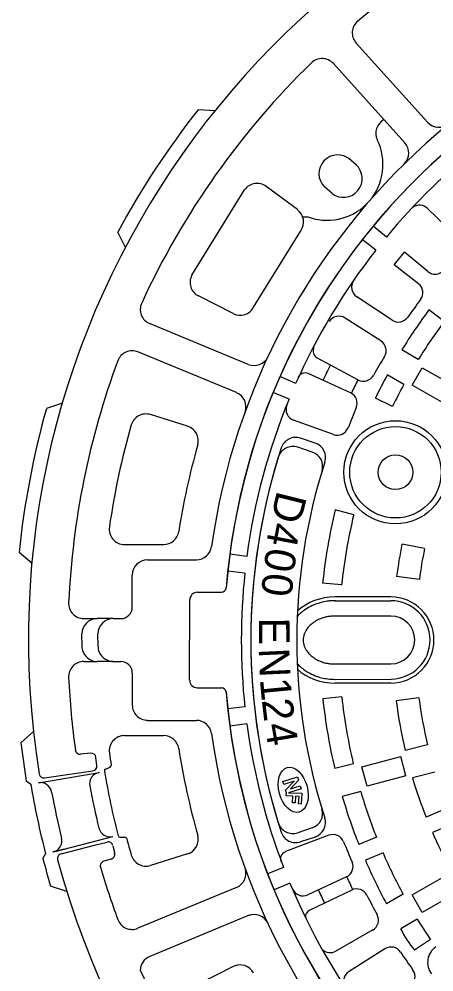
# Model space of a CAD drawing. Extents: x -7.1 to 10, y -5 to 6.
# Drawn here: x -2.462 to -1.897, y 0.265 to 1.564 of the extents above; entities that cross this region are included whole.
import ezdxf

# ---------------------------------------------------------------- set-up
doc = ezdxf.new("R2010")
doc.units = 0
doc.layers.add('Level 1', color=7, linetype='Continuous')

# ---------------------------------------------------------------- blocks, each defined once
blk = doc.blocks.new('CRAN')
at = {"layer": 'Level 1'}
for p, q in [((-3.652, 6.599), (-1.391, 7.083)), ((-3.232, 4.178), (-1.568, 4.4)), ((-1.568, 4.4), (-1.47, 3.52)), ((-3.114, 3.352), (-1.47, 3.52)), ((-2.949, 0.9), (-0.638, 0.965)), ((-2.949, -0.892), (-0.638, -0.957)), ((-3.114, -3.345), (-1.471, -3.52)), ((-1.568, -4.392), (-1.47, -3.512)), ((-3.232, -4.17), (-1.568, -4.392)), ((-3.652, -6.592), (-1.391, -7.076))]:
    blk.add_line(p, q, dxfattribs=at)
for centre, radius, start, end in [((-1.26, 6.472), 0.625, 11.0144, 102.0722), ((-3.521, 5.988), 0.625, 102.0722, 190.9368), ((-34.491, 0.004), 30.918, 8.7409, 10.9368), ((-3.315, 4.797), 0.625, 188.7409, 277.6056), ((-3.048, 2.731), 0.625, 96.0776, 184.9422), ((-34.473, 0.013), 30.918, 2.7463, 4.9422), ((-2.967, 1.524), 0.625, 182.7463, 271.611), ((-0.656, 1.589), 0.625, 271.611, 348.8242), ((-2.967, -1.517), 0.625, 88.389, 177.2537), ((-0.656, -1.582), 0.625, 11.1758, 88.389), ((-34.473, -0.006), 30.918, 355.0578, 357.2537), ((-3.048, -2.723), 0.625, 175.0578, 263.9224), ((-3.315, -4.79), 0.625, 82.3944, 171.2591), ((-34.491, 0.004), 30.918, 349.0632, 351.2591), ((-3.521, -5.981), 0.625, 169.0632, 257.9278), ((-1.26, -6.464), 0.625, 257.9278, 348.9856)]:
    blk.add_arc(centre, radius, start, end, dxfattribs=at)

msp = doc.modelspace()

# ---------------------------------------------------------------- linework, layer by layer
at = {"layer": 'Level 1'}
for p, q in [((-1.9053, 1.4229), (-2.0026, 1.5308)), ((-1.9363, 1.395), (-2.0336, 1.5029)), ((-2.1948, 1.4386), (-2.218, 1.44)), ((-2.002, 1.3642), (-2.0125, 1.3733)), ((-2.2265, 1.2145), (-2.1548, 1.3308)), ((-2.0826, 1.3038), (-2.1254, 1.3354)), ((-2.0353, 1.3257), (-2.0458, 1.3347)), ((-2.3169, 1.2524), (-2.3274, 1.2732)), ((-2.1423, 1.1709), (-2.0781, 1.275)), ((-1.9614, 1.2665), (-1.9795, 1.2814)), ((-1.9759, 1.2486), (-1.9943, 1.263)), ((-2.1701, 1.1622), (-2.2175, 1.1862)), ((-1.9689, 1.1248), (-2.0175, 1.1561)), ((-1.8829, 1.1515), (-1.9035, 1.1674)), ((-2.1496, 1.0929), (-2.2839, 1.1485)), ((-2.1656, 1.0544), (-2.2998, 1.11)), ((-1.918, 1.0996), (-1.9404, 1.1128)), ((-2.0002, 1.0719), (-2.056, 1.1019)), ((-2.0104, 1.0542), (-2.0681, 1.0804)), ((-1.9376, 1.0657), (-1.9602, 1.0788)), ((-1.9263, 1.0647), (-1.9126, 1.0884)), ((-1.9126, 1.0884), (-1.8652, 1.061)), ((-2.085, 1.0668), (-2.1065, 1.0763)), ((-2.0941, 1.0456), (-2.1158, 1.0546)), ((-1.8789, 1.0374), (-1.9263, 1.0647)), ((-2.4025, 1.0401), (-2.4245, 1.0326)), ((-1.953, 1.0357), (-1.9765, 1.0471)), ((-2.2322, 1.0087), (-2.2828, 1.0245)), ((-2.0336, 0.9973), (-2.0879, 1.017)), ((-2.0585, 0.9857), (-2.0783, 0.9923)), ((-2.0624, 0.9733), (-2.0822, 0.9799)), ((-2.006, 0.888), (-2.0311, 0.8948)), ((-2.3182, 0.8475), (-2.2649, 0.8475)), ((-1.9096, 0.8418), (-1.9402, 0.848)), ((-2.444, 0.8214), (-2.4617, 0.8366)), ((-2.1515, 0.8313), (-2.1747, 0.8344)), ((-2.2867, 0.8266), (-2.2203, 0.8266)), ((-2.3075, 0.7621), (-2.3075, 0.8058)), ((-2.1542, 0.8085), (-2.1775, 0.811)), ((-2.0224, 0.7923), (-2.0483, 0.7949)), ((-1.9166, 0.7999), (-1.9476, 0.804)), ((-2.2189, 0.7823), (-2.1862, 0.7823)), ((-2.2295, 0.6626), (-2.2294, 0.7719)), ((-2.0318, 0.7708), (-1.9554, 0.7708)), ((-1.9554, 0.776), (-2.0314, 0.776)), ((-2.3735, 0.7464), (-2.3554, 0.7464)), ((-2.3335, 0.7464), (-2.3554, 0.7464)), ((-2.3335, 0.7464), (-2.3231, 0.7464)), ((-1.9554, 0.7499), (-2.0314, 0.7499)), ((-2.3762, 0.7173), (-2.3762, 0.7256)), ((-2.3762, 0.7172), (-2.3762, 0.7089)), ((-2.3544, 0.7173), (-2.3544, 0.7256)), ((-2.3544, 0.7172), (-2.3544, 0.7089)), ((-2.3735, 0.688), (-2.3554, 0.688)), ((-2.3335, 0.688), (-2.3554, 0.688)), ((-2.3335, 0.688), (-2.3231, 0.688)), ((-2.033, 0.6846), (-1.9553, 0.6848)), ((-2.3075, 0.6724), (-2.3075, 0.6287)), ((-2.0318, 0.6637), (-1.9552, 0.664)), ((-2.2191, 0.6522), (-2.1862, 0.6521)), ((-1.9554, 0.6585), (-2.0314, 0.6585)), ((-2.0222, 0.6398), (-2.0481, 0.6371)), ((-1.9171, 0.6385), (-1.9481, 0.6346)), ((-2.1542, 0.626), (-2.1775, 0.6235)), ((-2.2867, 0.6078), (-2.2203, 0.6078)), ((-2.1515, 0.6032), (-2.1747, 0.6)), ((-2.4419, 0.5925), (-2.4593, 0.5771)), ((-2.3182, 0.587), (-2.2649, 0.587)), ((-1.9056, 0.5746), (-1.9359, 0.5668)), ((-2.3641, 0.563), (-2.378, 0.5616)), ((-1.9948, 0.5445), (-1.9419, 0.5586)), ((-1.9349, 0.5322), (-1.9419, 0.5586)), ((-2.3557, 0.5462), (-2.357, 0.5573)), ((-2.0065, 0.5486), (-2.0317, 0.5421)), ((-2.4353, 0.5227), (-2.3527, 0.5368)), ((-2.4269, 0.5293), (-2.3612, 0.539)), ((-2.344, 0.5415), (-2.3379, 0.5441)), ((-1.9877, 0.518), (-1.9948, 0.5445)), ((-1.8957, 0.5374), (-1.9259, 0.5294)), ((-2.4519, 0.5252), (-2.4459, 0.5209)), ((-2.1024, 0.5243), (-2.0824, 0.5306)), ((-2.1012, 0.5203), (-2.1024, 0.5243)), ((-2.0873, 0.5248), (-2.1012, 0.5203)), ((-2.0988, 0.5126), (-2.0873, 0.5248)), ((-2.081, 0.5262), (-2.0922, 0.5144)), ((-2.0824, 0.5306), (-2.081, 0.5262)), ((-1.9349, 0.5322), (-1.9877, 0.518)), ((-2.0976, 0.5088), (-2.0988, 0.5126)), ((-2.0978, 0.505), (-2.0976, 0.5088)), ((-2.0774, 0.5146), (-2.0947, 0.5092)), ((-2.0947, 0.5092), (-2.0767, 0.5084)), ((-2.0922, 0.5144), (-2.0787, 0.5187)), ((-2.0787, 0.5187), (-2.0774, 0.5146)), ((-2.0767, 0.5084), (-2.0774, 0.4937)), ((-1.9964, 0.5107), (-2.0216, 0.504)), ((-2.0889, 0.5046), (-2.0978, 0.505)), ((-2.0893, 0.4955), (-2.0889, 0.5046)), ((-2.0856, 0.4954), (-2.0893, 0.4955)), ((-2.0852, 0.5045), (-2.0856, 0.4954)), ((-2.0805, 0.5042), (-2.0852, 0.5045)), ((-2.081, 0.4939), (-2.0805, 0.5042)), ((-2.0774, 0.4937), (-2.081, 0.4939)), ((-1.8785, 0.4879), (-1.9074, 0.476)), ((-2.0625, 0.4612), (-2.0822, 0.4546)), ((-1.8698, 0.467), (-1.8987, 0.455)), ((-2.4128, 0.4291), (-2.3339, 0.4495)), ((-2.3592, 0.4375), (-2.3419, 0.4419)), ((-2.3244, 0.4487), (-2.3177, 0.4488)), ((-2.0397, 0.4511), (-2.0991, 0.4289)), ((-2.0585, 0.4488), (-2.0783, 0.4422)), ((-1.9749, 0.4484), (-1.999, 0.4385)), ((-2.4001, 0.4324), (-2.4151, 0.4285)), ((-2.4046, 0.4258), (-2.3592, 0.4375)), ((-2.334, 0.437), (-2.3315, 0.4265)), ((-2.4293, 0.4194), (-2.4256, 0.4258)), ((-2.4151, 0.4285), (-2.416, 0.4282)), ((-2.3361, 0.4187), (-2.3464, 0.4157)), ((-2.2322, 0.4258), (-2.2828, 0.41)), ((-1.9661, 0.4271), (-1.9901, 0.4171)), ((-2.1014, 0.4072), (-2.1233, 0.3988)), ((-2.0159, 0.3945), (-2.0683, 0.37)), ((-1.9263, 0.3698), (-1.8789, 0.3971)), ((-2.3966, 0.3745), (-2.4188, 0.3818)), ((-2.1655, 0.3801), (-2.2998, 0.3245)), ((-2.0929, 0.3859), (-2.1145, 0.3769)), ((-2.0086, 0.3765), (-2.0658, 0.3492)), ((-1.9387, 0.3707), (-1.9613, 0.3579)), ((-1.9126, 0.3461), (-1.9263, 0.3698)), ((-1.8652, 0.3734), (-1.9126, 0.3461)), ((-2.1484, 0.3421), (-2.2838, 0.286)), ((-1.9194, 0.3367), (-1.942, 0.3238)), ((-1.9801, 0.3221), (-2.0302, 0.2932)), ((-1.9016, 0.309), (-1.9233, 0.2946)), ((-2.1701, 0.2723), (-2.2175, 0.2483))]:
    msp.add_line(p, q, dxfattribs=at)
for radius in [0.0703, 0.0623, 0.0237]:
    msp.add_circle((-1.9491, 0.9459), radius, dxfattribs=at)
for centre, radius, start, end in [((-1.2973, 0.7173), 1.1516, 195.0717, 189.1227), ((-1.2971, 0.7172), 1.0983, 112.8646, 129.8224), ((-1.2971, 0.7172), 0.9115, 12.3185, 171.9696), ((-1.2971, 0.7172), 0.8854, 5.6674, 175.3947), ((-1.9872, 1.5447), 0.0208, 129.8224, 222.04), ((-1.2971, 0.7172), 0.8854, 114.6615, 175.3947), ((-2.0491, 1.4889), 0.0208, 42.04, 134.2547), ((-1.2971, 0.7172), 1.0983, 134.2189, 155.2815), ((-1.2977, 0.717), 1.1703, 141.8462, 151.6251), ((-1.9551, 1.408), 0.0208, 117.4512, 206.0842), ((-1.8899, 1.4368), 0.0208, 222.04, 309.4803), ((-2.0422, 1.3654), 0.0761, 252.3344, 26.0842), ((-1.2971, 0.7172), 0.862, 128.262, 140.418), ((-1.9518, 1.381), 0.0208, 314.6034, 42.04), ((-2.0279, 1.3529), 0.0255, 48.4395, 225.3147), ((-2.02, 1.3461), 0.0255, 233.0279, 48.4318), ((-2.1378, 1.3187), 0.0208, 53.4552, 144.6097), ((-2.0951, 1.287), 0.0208, 324.6638, 53.4552), ((-2.0716, 1.273), 0.0208, 72.3344, 100.1249), ((-1.2971, 0.7172), 0.862, 141.9456, 156.078), ((-2.2081, 1.2047), 0.0208, 152.0353, 243.1452), ((-2.2759, 1.1677), 0.0208, 155.2815, 247.5), ((-2.1607, 1.1807), 0.0208, 243.1452, 331.9406), ((-2.026, 1.143), 0.0156, 57.2121, 148.2699), ((-1.2971, 0.7172), 0.7552, 143.415, 148.4128), ((-1.2971, 0.7172), 0.7292, 143.4475, 148.3753), ((-1.9774, 1.1117), 0.0156, 328.3474, 57.2121), ((-2.3078, 1.0907), 0.0208, 67.5, 159.7138), ((-2.051, 1.1111), 0.0104, 150.9692, 241.6787), ((-1.2971, 0.7172), 1.0983, 159.7138, 177.3343), ((-2.1416, 1.1121), 0.0208, 247.5, 334.9404), ((-1.2971, 0.7172), 0.8301, 153.1524, 154.7577), ((-1.3061, 0.6979), 0.7729, 148.3474, 150.5433), ((-2.0724, 1.0709), 0.0104, 65.5686, 156.2781), ((-1.9928, 1.0856), 0.0156, 241.6787, 330.5433), ((-1.2971, 0.7172), 0.7552, 151.3995, 154.1013), ((-1.2971, 0.7172), 0.7875, 153.2323, 154.7184), ((-1.2971, 0.7172), 0.7292, 151.4545, 154.1013), ((-2.1735, 1.0351), 0.0208, 340.0635, 67.5), ((-2.0169, 1.0399), 0.0156, 336.704, 65.5686), ((-1.2971, 0.7172), 0.862, 157.6056, 172.3944), ((-1.2976, 0.7168), 1.1703, 164.3462, 174.1251), ((-2.0826, 1.0317), 0.0156, 158.9774, 250.0352), ((-1.2926, 0.7281), 0.7729, 156.704, 158.8998), ((-2.289, 1.0046), 0.0208, 72.6555, 164.0223), ((-1.2949, 0.72), 1.0548, 164.0223, 171.7512), ((-2.2384, 0.9888), 0.0208, 344.0255, 72.6555), ((-2.0283, 1.012), 0.0156, 250.0352, 338.8998), ((-2.0849, 0.9726), 0.0208, 71.5, 162.0405), ((-1.2921, 0.7179), 0.9635, 164.0255, 171.2099), ((-1.2971, 0.7172), 0.849, 162.0405, 197.9595), ((-2.0888, 0.9602), 0.0208, 71.5, 162.9416), ((-2.0651, 0.966), 0.0208, 342.0545, 71.5), ((-1.2971, 0.7172), 0.849, 162.9416, 197.0584), ((-2.069, 0.9536), 0.0208, 342.9788, 71.5), ((-1.2971, 0.7172), 0.7865, 162.0545, 197.9455), ((-1.2971, 0.7172), 0.7552, 166.3995, 174.0937), ((-1.2971, 0.7172), 0.7292, 166.4545, 174.0937), ((-2.3182, 0.8683), 0.0208, 171.7512, 270), ((-2.2649, 0.8683), 0.0208, 270, 351.2099), ((-2.2203, 0.8475), 0.0208, 270, 351.9696), ((-1.2971, 0.7172), 0.6563, 168.5057, 172.4024), ((-1.2971, 0.7172), 0.625, 168.5057, 172.4024), ((-2.2867, 0.8058), 0.0208, 90, 180), ((-1.2971, 0.7172), 0.862, 173.922, 186.078), ((-2.2189, 0.7719), 0.0104, 90, 179.9516), ((-2.1862, 0.7889), 0.00651, 270, 355.3947), ((-1.2975, 0.7168), 0.885, 175.3618, 175.3623), ((-2.3735, 0.7673), 0.0208, 177.3343, 270), ((-1.9554, 0.7174), 0.0586, 359.8576, 90), ((-1.9554, 0.7174), 0.0534, 270.2162, 90.0016), ((-2.3231, 0.7621), 0.0156, 270, 0), ((-2.3554, 0.7256), 0.0208, 90, 180), ((-2.3335, 0.7256), 0.0208, 90, 180), ((-1.9554, 0.7174), 0.0326, 270.1964, 90.0023), ((-1.9554, 0.7173), 0.0586, 270.1038, 0.2462), ((-2.3554, 0.7089), 0.0208, 180.0017, 270.0017), ((-2.3335, 0.7089), 0.0208, 180.0017, 270.0017), ((-2.3735, 0.6672), 0.0208, 90.0017, 182.6674), ((-2.3231, 0.6724), 0.0156, 0.0017, 90.0017), ((-1.2971, 0.7173), 1.0983, 182.6674, 187.8577), ((-2.219, 0.6626), 0.0104, 179.9516, 269.9287), ((-2.1862, 0.6456), 0.00651, 4.6051, 89.9287), ((-1.2975, 0.7168), 0.885, 184.5129, 184.5767), ((-1.2971, 0.7172), 0.8854, 184.6051, 245.3048), ((-1.2971, 0.7172), 0.8854, 184.6051, 354.3326), ((-1.2971, 0.7172), 0.7552, 186.0942, 193.4128), ((-1.2971, 0.7172), 0.7292, 186.0942, 193.3753), ((-1.2971, 0.7172), 0.625, 187.2364, 193.1939), ((-2.2867, 0.6287), 0.0208, 180.0017, 270.0017), ((-1.2971, 0.7172), 0.6563, 187.2364, 193.2544), ((-2.2203, 0.587), 0.0208, 8.0305, 90.0017), ((-1.2971, 0.7172), 0.862, 187.6056, 201.078), ((-2.3182, 0.5662), 0.0208, 90.0017, 188.2505), ((-2.2649, 0.5662), 0.0208, 8.7918, 90.0017), ((-1.2971, 0.7172), 0.9115, 188.0305, 347.6848), ((-1.2974, 0.7166), 1.1703, 186.8462, 189.4179), ((-2.3787, 0.5681), 0.00651, 187.8577, 275.7079), ((-2.3635, 0.5565), 0.00651, 6.7129, 95.7079), ((-1.2949, 0.7145), 1.0548, 188.2505, 189.1417), ((-1.2921, 0.7166), 0.9635, 188.7918, 195.9762), ((-2.3622, 0.5454), 0.00651, 278.4099, 6.7129), ((-2.3389, 0.5465), 0.0026, 293.4978, 9.1417), ((-2.4279, 0.5357), 0.00651, 189.1227, 278.4099), ((-2.3501, 0.5214), 0.0156, 99.6988, 190.6305), ((-2.343, 0.5391), 0.0026, 113.4978, 189.5032), ((-1.2949, 0.7145), 1.0652, 189.5032, 194.3422), ((-1.2974, 0.7166), 1.1651, 189.6728, 194.4575), ((-2.4327, 0.5073), 0.0156, 10.5009, 99.6988), ((-1.2971, 0.7172), 0.6563, 196.6317, 201.5646), ((-1.2938, 0.7184), 1.1427, 190.5009, 193.7235), ((-1.3064, 0.7173), 1.0776, 190.6305, 193.7681), ((-1.2971, 0.7172), 0.7292, 196.4545, 201.638), ((-1.2971, 0.7172), 0.7552, 196.3995, 201.6608), ((-2.0691, 0.481), 0.0208, 288.4944, 17.0157), ((-2.0888, 0.4744), 0.0208, 197.0529, 288.4944), ((-2.0652, 0.4686), 0.0208, 288.4944, 17.94), ((-2.3378, 0.4646), 0.0156, 193.7681, 284.4818), ((-2.0849, 0.4619), 0.0208, 197.9539, 288.4944), ((-1.2971, 0.7172), 0.6563, 203.552, 208.2544), ((-2.419, 0.4436), 0.0156, 284.4818, 13.7235), ((-2.3403, 0.4356), 0.00651, 13.0978, 104.054), ((-2.3244, 0.4513), 0.0026, 194.3422, 270.4268), ((-2.3177, 0.4462), 0.0026, 14.7031, 90.4268), ((-1.2949, 0.7145), 1.0548, 194.7031, 195.9794), ((-2.2384, 0.4457), 0.0208, 287.3462, 15.9762), ((-2.0342, 0.4365), 0.0156, 21.704, 110.5686), ((-1.3016, 0.7281), 0.7729, 201.704, 203.8998), ((-2.0954, 0.4191), 0.0104, 110.5686, 201.2781), ((-1.2974, 0.7166), 1.1703, 194.7126, 196.6251), ((-2.403, 0.4195), 0.00651, 104.4818, 195.0717), ((-2.3446, 0.4095), 0.00651, 106.1063, 196.3778), ((-2.3379, 0.425), 0.00651, 286.1063, 13.0978), ((-2.289, 0.4299), 0.0208, 195.9794, 287.3462), ((-1.2971, 0.7172), 0.7552, 203.415, 208.4128), ((-1.2971, 0.7172), 0.7292, 203.4475, 208.3753), ((-1.2971, 0.7173), 1.0983, 196.3778, 200.2879), ((-2.1735, 0.3994), 0.0208, 292.5017, 16.6228), ((-2.0225, 0.4086), 0.0156, 295.0352, 23.8998), ((-1.2971, 0.7172), 0.7875, 204.1803, 205.5909), ((-1.2971, 0.7172), 0.862, 202.6056, 216.7344), ((-2.0749, 0.3842), 0.0156, 203.9774, 295.0352), ((-1.2971, 0.7172), 0.8301, 204.2248, 205.5852), ((-2.0019, 0.3624), 0.0156, 26.6109, 115.4756), ((-1.2969, 0.7156), 0.7729, 206.6109, 208.8068), ((-2.1416, 0.3224), 0.0208, 25.1349, 112.5017), ((-2.0614, 0.3398), 0.0104, 115.4756, 183.3766), ((-1.9879, 0.3356), 0.0156, 299.9422, 28.8068), ((-2.3078, 0.3437), 0.0208, 200.2879, 292.5017), ((-1.2974, 0.7172), 0.7292, 211.4545, 214.0482), ((-1.8041, 0.3918), 0.1538, 206.2435, 219.1861), ((-1.8793, 0.2778), 0.026, 125, 217.0904), ((-2.2759, 0.2667), 0.0208, 112.5017, 178.9543), ((-2.038, 0.3068), 0.0156, 225.2442, 299.9422), ((-2.1607, 0.2537), 0.0208, 28.0611, 116.8565), ((-1.2958, 0.7194), 1.0983, 204.3143, 222.8654)]:
    msp.add_arc(centre, radius, start, end, dxfattribs=at)
for start_param, end_param in [(4.712389, 5.541257), (0.741928, 1.570796)]:
    msp.add_ellipse((-2.0314, 0.7172), major_axis=(-0.0694, 0), ratio=0.846565, start_param=start_param, end_param=end_param, dxfattribs=at)
msp.add_ellipse((-2.0883, 0.5131), major_axis=(-0.0082, 0.0304), ratio=0.617254, dxfattribs=at)
for points in [[(-2.031, 0.7708), (-2.0315, 0.7708), (-2.0319, 0.7708), (-2.0388, 0.7707), (-2.0454, 0.7698), (-2.0578, 0.7663), (-2.0636, 0.7638), (-2.0742, 0.7575), (-2.0789, 0.7536), (-2.0828, 0.7493), (-2.0829, 0.7492), (-2.0829, 0.7491)], [(-2.0314, 0.7499), (-2.0338, 0.7499), (-2.0361, 0.7498), (-2.0429, 0.7489), (-2.0472, 0.7478), (-2.0551, 0.7447), (-2.0587, 0.7427), (-2.0647, 0.7382), (-2.0673, 0.7357), (-2.0712, 0.7304), (-2.0726, 0.7277), (-2.0743, 0.7224), (-2.0748, 0.7198), (-2.0748, 0.7172), (-2.0748, 0.7146), (-2.0743, 0.7119), (-2.0725, 0.7065), (-2.071, 0.7038), (-2.067, 0.6986), (-2.0645, 0.6961), (-2.0583, 0.6916), (-2.0547, 0.6896), (-2.0468, 0.6865), (-2.0425, 0.6855), (-2.0364, 0.6847), (-2.0347, 0.6846), (-2.033, 0.6846)], [(-2.0829, 0.6853), (-2.081, 0.6832), (-2.0789, 0.6811), (-2.072, 0.6754), (-2.0667, 0.6722), (-2.0551, 0.6672), (-2.0488, 0.6654), (-2.0384, 0.6639), (-2.0344, 0.6637), (-2.0304, 0.6637)]]:
    msp.add_open_spline(points, degree=3, dxfattribs=at)

# ---------------------------------------------------------------- block references
at = {"layer": 'Level 1', "yscale": 0.024999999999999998}
for p, xscale, rotation in [((-1.8996, 1.3337), 0.024999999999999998, 134.33999999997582), ((-1.9136, 0.1148), 0.025, -135.66)]:
    msp.add_blockref('CRAN', p, dxfattribs=dict(at, xscale=xscale, rotation=rotation))

# ---------------------------------------------------------------- texts
at = {"layer": 'Level 1'}
for s, rotation, p in [('D', 256.03, (-2.1099, 0.9221)), ('4', 259.13, (-2.1194, 0.8793)), ('0', 260.0713, (-2.124, 0.8448)), ('0', 263.1584, (-2.1287, 0.8103)), ('E', 270.5, (-2.1352, 0.7477)), ('N', 272.5962, (-2.1355, 0.7056)), ('1', 275.4274, (-2.1339, 0.6639)), ('2', 276.6872, (-2.1312, 0.6355)), ('4', 279.798, (-2.1276, 0.6016))]:
    msp.add_text(s, height=0.0417, rotation=rotation, dxfattribs=at).set_placement(p)

doc.saveas('drawing.dxf')
